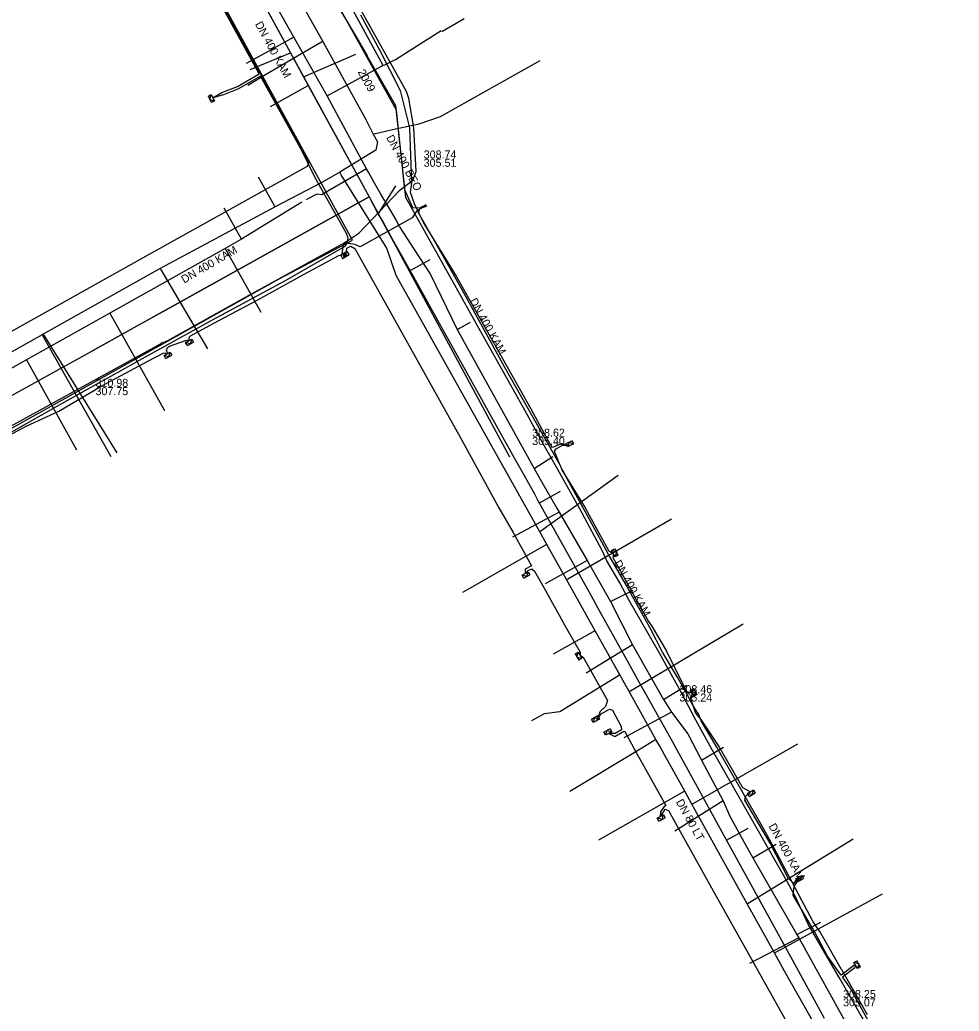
# Model space of a CAD drawing. Extents: x -600391 to -599491, y -1160176 to -1159402.
# Drawn here: x -600248.7 to -600154.7, y -1160007 to -1159907.9 of the extents above; entities that cross this region are included whole.
import ezdxf

# ---------------------------------------------------------------- set-up
doc = ezdxf.new("R2010")
doc.units = 0
for name, color, linetype in [('28', 7, 'Continuous'), ('31', 7, 'Continuous'), ('CETIN_linie', 7, 'Continuous'), ('Vrstva 1', 7, 'Continuous'), ('Vrstva 12', 7, 'Continuous'), ('Vrstva 13', 7, 'Continuous'), ('Vrstva 15', 7, 'Continuous'), ('Vrstva 16', 7, 'Continuous'), ('Vrstva 19', 7, 'Continuous'), ('Vrstva 42', 7, 'Continuous'), ('Vrstva 43', 7, 'Continuous'), ('Vrstva 44', 7, 'Continuous'), ('Vrstva 55', 7, 'Continuous'), ('Vrstva 58', 7, 'Continuous'), ('Vrstva 9', 7, 'Continuous')]:
    doc.layers.add(name, color=color, linetype=linetype)

# ---------------------------------------------------------------- blocks, each defined once
blk = doc.blocks.new('NN630')
at = {"layer": '31'}
for points in [[(0, -0.7), (-0.7, 0)], [(-0.7, -0.7), (-0.7, 0), (0.7, 0), (0.7, -0.7)], [(-0.7, -0.7), (0.7, -0.7)], [(0, -0.7), (0.7, 0)]]:
    blk.add_lwpolyline(points, dxfattribs=at)
blk = doc.blocks.new('NN620')
at = {"layer": '28'}
for points in [[(0.75, 0), (-0.75, 0)], [(-0.75, 0), (-0.75, -0.75)], [(0.75, -0.75), (0.75, 0)], [(-0.75, -0.75), (0.75, -0.75)], [(0.37, -0.18), (-0.38, -0.18)], [(-0.38, -0.18), (-0.38, -0.56)], [(-0.38, -0.56), (0.37, -0.56)], [(0.32, -0.23), (-0.33, -0.23)], [(-0.33, -0.23), (-0.33, -0.51)], [(-0.33, -0.51), (0.32, -0.51)], [(0.27, -0.27), (-0.28, -0.27)], [(-0.28, -0.27), (-0.28, -0.46)], [(-0.28, -0.46), (0.27, -0.46)], [(0.23, -0.32), (-0.23, -0.32)], [(-0.23, -0.32), (-0.23, -0.42)], [(-0.23, -0.42), (0.23, -0.42)], [(-0.19, -0.37), (0.19, -0.37)], [(0.23, -0.42), (0.23, -0.32)], [(0.27, -0.46), (0.27, -0.27)], [(0.32, -0.51), (0.32, -0.23)], [(0.37, -0.56), (0.37, -0.18)]]:
    blk.add_lwpolyline(points, dxfattribs=at)

msp = doc.modelspace()

# ---------------------------------------------------------------- linework, layer by layer
at = {"layer": 'CETIN_linie'}
for p, q in [((-600181.06, -1159977.93), (-600182.53, -1159975.15)), ((-600171.88, -1159994.13), (-600176.71, -1159985.63)), ((-600156.94, -1160020.68), (-600166.6, -1160003.83))]:
    msp.add_line(p, q, dxfattribs=at)
for points in [[(-600229.22, -1159878.49), (-600229.51, -1159878.56), (-600231.76, -1159879.81), (-600225.26, -1159891.62), (-600224.22, -1159891.95), (-600223.98, -1159892.52), (-600224.15, -1159893.48), (-600217.61, -1159905.3), (-600215.04, -1159909.61), (-600213.93, -1159911.53)], [(-600195.003, -1159952.628), (-600196.31, -1159950.3), (-600198.14, -1159947.01), (-600203.06, -1159938.22), (-600203.1, -1159938.16), (-600210.05, -1159925.68), (-600211.06, -1159916.52), (-600213.93, -1159911.53)], [(-600190.41, -1159960.98), (-600192.65, -1159956.82), (-600195.003, -1159952.628)], [(-600182.53, -1159975.15), (-600184.7, -1159971.24), (-600187.71, -1159965.99), (-600188.67, -1159964.22), (-600189.97, -1159962.01), (-600190.41, -1159960.98)], [(-600176.71, -1159985.63), (-600179.43, -1159980.91), (-600181.06, -1159977.93)], [(-600166.6, -1160003.83), (-600169.8, -1159998.34), (-600171.08, -1159995.6), (-600171.88, -1159994.13)]]:
    msp.add_lwpolyline(points, dxfattribs=at)
at = {"layer": 'Vrstva 1'}
for points in [[(-600227.38, -1159900.62), (-600213.74, -1159925.63)], [(-600225.623, -1159912.896), (-600221.592, -1159911.232)], [(-600220.3, -1159913.602), (-600215.079, -1159911.361)], [(-600223.592, -1159916.572), (-600219.821, -1159914.48)], [(-600212.817, -1159927.336), (-600211.075, -1159924.52)], [(-600213.74, -1159925.63), (-600241.48, -1159941.06)], [(-600213.74, -1159925.63), (-600199.68, -1159951.62)], [(-600207.656, -1159931.9), (-600209.718, -1159933.049)], [(-600194.628, -1159955.067), (-600196.741, -1159956.233)], [(-600175.847, -1159988.76), (-600178.01, -1159989.96)]]:
    msp.add_lwpolyline(points, dxfattribs=at)
at = {"layer": 'Vrstva 13'}
for p, q in [((-600216.681, -1159923.158), (-600218.452, -1159924.183)), ((-600216.52, -1159923.42), (-600216.681, -1159923.158)), ((-600211.95, -1159930.74), (-600216.52, -1159923.42)), ((-600234.63, -1159932.796), (-600229.9, -1159940.808)), ((-600246.455, -1159939.412), (-600239.571, -1159951.564)), ((-600246.329, -1159939.337), (-600238.986, -1159951.215))]:
    msp.add_line(p, q, dxfattribs=at)
for points in [[(-600235.77, -1159878.73), (-600234.17, -1159881.51), (-600232.367, -1159884.809), (-600230.48, -1159888.26), (-600223.703, -1159900.561), (-600223.01, -1159901.82), (-600218.371, -1159910.085), (-600214.068, -1159917.894), (-600213.34, -1159919.34), (-600212.9, -1159920.13), (-600213.06, -1159920.96), (-600216.681, -1159923.158)], [(-600218.371, -1159910.085), (-600218.497, -1159910.161), (-600223.929, -1159913.33), (-600225.883, -1159914.469)], [(-600213.34, -1159919.34), (-600213.108, -1159919.284), (-600211.41, -1159918.88), (-600208.74, -1159918.3), (-600206.59, -1159917.58), (-600196.63, -1159911.975)], [(-600218.452, -1159924.183), (-600223.136, -1159926.626), (-600234.63, -1159932.796), (-600246.329, -1159939.337), (-600246.455, -1159939.412), (-600258.475, -1159946.157), (-600268.657, -1159951.909), (-600271.06, -1159953.3), (-600271.84, -1159953.73)], [(-600223.136, -1159926.626), (-600223.211, -1159926.502), (-600224.793, -1159923.665)], [(-600154.709, -1160034.079), (-600157.474, -1160029.081), (-600161.178, -1160022.525), (-600161.396, -1160022.14), (-600162.074, -1160020.939), (-600165.91, -1160014.151), (-600169.665, -1160007.505), (-600172.186, -1160003.043), (-600173.2, -1160001.214), (-600175.931, -1159996.29), (-600181.445, -1159986.347), (-600182.167, -1159985.045), (-600184.183, -1159981.41), (-600184.671, -1159980.537), (-600185.044, -1159979.869), (-600187.721, -1159975.079), (-600188.649, -1159973.419), (-600191.123, -1159968.992), (-600193.986, -1159963.868), (-600195.946, -1159960.361), (-600196.653, -1159959.101), (-600211.015, -1159933.486), (-600211.95, -1159930.74)], [(-600196.653, -1159959.101), (-600196.546, -1159959.024), (-600188.833, -1159953.438)], [(-600193.986, -1159963.868), (-600193.852, -1159963.796), (-600183.488, -1159957.804)], [(-600195.946, -1159960.361), (-600196.15, -1159960.479), (-600204.408, -1159965.177)], [(-600191.123, -1159968.992), (-600191.316, -1159969.1), (-600195.34, -1159971.346)], [(-600187.721, -1159975.079), (-600187.596, -1159975.004), (-600176.334, -1159968.316)], [(-600188.649, -1159973.419), (-600188.774, -1159973.497), (-600194.665, -1159977.106), (-600196.225, -1159977.317), (-600197.506, -1159978.016)], [(-600185.044, -1159979.869), (-600185.27, -1159980.006), (-600187.221, -1159981.188), (-600193.65, -1159985.062)], [(-600181.445, -1159986.347), (-600181.312, -1159986.273), (-600170.837, -1159980.292)], [(-600182.167, -1159985.045), (-600182.349, -1159985.149), (-600190.803, -1159989.944)], [(-600175.931, -1159996.29), (-600175.815, -1159996.221), (-600165.309, -1159989.808)], [(-600173.2, -1160001.214), (-600173.066, -1160001.143), (-600162.376, -1159995.313)]]:
    msp.add_lwpolyline(points, dxfattribs=at)
at = {"layer": 'Vrstva 16'}
for points in [[(-600220.454, -1159926.15), (-600226.51, -1159929.85), (-600228.15, -1159930.77), (-600239.67, -1159937.23), (-600248.01, -1159941.9), (-600257.72, -1159947.35), (-600266.63, -1159952.34), (-600269.18, -1159953.76), (-600270.17, -1159954.32), (-600274.87, -1159956.95), (-600277.66, -1159958.52), (-600294.25, -1159967.81), (-600301.53, -1159971.89), (-600306.26, -1159974.55)], [(-600226.51, -1159929.85), (-600228.25, -1159926.76)], [(-600228.15, -1159930.77), (-600224.58, -1159937.13)], [(-600239.67, -1159937.23), (-600234.21, -1159946.99)], [(-600248.01, -1159941.9), (-600243.02, -1159950.92)]]:
    msp.add_lwpolyline(points, dxfattribs=at)
at = {"layer": 'Vrstva 19'}
msp.add_line((-600206.46, -1159909.08), (-600204.238, -1159907.796), dxfattribs=at)
for points in [[(-600210.69, -1159928.6), (-600211.071, -1159927.848), (-600212.567, -1159925.332), (-600213.206, -1159924.258), (-600213.809, -1159923.163), (-600213.997, -1159922.82), (-600217.918, -1159915.528), (-600221.258, -1159909.637), (-600225.65, -1159901.89), (-600226.441, -1159900.495), (-600227.057, -1159899.408), (-600227.668, -1159898.317), (-600233.004, -1159888.777), (-600237.397, -1159880.924), (-600237.874, -1159880.113), (-600243.124, -1159871.345), (-600260.994, -1159839.129), (-600261.405, -1159838.349)], [(-600225.044, -1159891.003), (-600224.158, -1159891.278), (-600216.76, -1159904.352), (-600212.351, -1159912.452)], [(-600212.174, -1159912.407), (-600211.104, -1159911.881), (-600206.514, -1159908.994)], [(-600221.258, -1159909.637), (-600224.126, -1159911.251), (-600226.038, -1159912.297)], [(-600217.918, -1159915.528), (-600212.505, -1159912.541)], [(-600212.505, -1159912.541), (-600212.351, -1159912.452), (-600212.174, -1159912.407)], [(-600213.997, -1159922.82), (-600217.852, -1159925.042), (-600218.194, -1159925.244), (-600218.464, -1159925.405), (-600218.959, -1159925.354), (-600219.301, -1159925.523), (-600220.025, -1159925.909)], [(-600210.69, -1159928.6), (-600209.233, -1159930.867), (-600207.61, -1159933.39), (-600204.93, -1159938.88), (-600197.21, -1159952.77), (-600196.46, -1159954.15), (-600194.958, -1159956.747), (-600194.73, -1159957.14), (-600191.92, -1159961.97), (-600189.6, -1159966.08), (-600187.38, -1159970.41), (-600184.29, -1159975.86), (-600183.48, -1159977.13), (-600181.841, -1159979.296), (-600180.487, -1159981.944), (-600178.32, -1159986.01), (-600177.686, -1159987.46), (-600176.241, -1159990.089), (-600175.357, -1159991.697), (-600170.951, -1159999.359), (-600170.74, -1159999.709), (-600162.476, -1160014.618)], [(-600204.93, -1159938.88), (-600203.587, -1159938.131)], [(-600197.21, -1159952.77), (-600195.349, -1159951.573)], [(-600194.73, -1159957.14), (-600199.39, -1159959.65)], [(-600191.92, -1159961.97), (-600196.119, -1159964.292)], [(-600189.6, -1159966.08), (-600187.31, -1159964.93)], [(-600187.38, -1159970.41), (-600190.12, -1159972.08), (-600192.037, -1159973.248)], [(-600184.29, -1159975.86), (-600181.95, -1159974.43)], [(-600183.48, -1159977.13), (-600188.27, -1159979.72)], [(-600180.487, -1159981.944), (-600178.3, -1159980.626)], [(-600178.32, -1159986.01), (-600183.14, -1159989.03)], [(-600175.357, -1159991.697), (-600173.018, -1159990.336)], [(-600170.951, -1159999.359), (-600168.554, -1159998.124)], [(-600170.74, -1159999.709), (-600175.683, -1160002.273)]]:
    msp.add_lwpolyline(points, dxfattribs=at)
at = {"layer": 'Vrstva 42'}
for points in [[(-600216.424, -1159931.321), (-600216.308, -1159930.424), (-600216.054, -1159930.101), (-600214.752, -1159929.245), (-600210.643, -1159924.902), (-600209.361, -1159923.955), (-600209.02, -1159923.095), (-600209.257, -1159918.717), (-600209.765, -1159915.778), (-600209.981, -1159915.075), (-600215.817, -1159904.626), (-600215.065, -1159904.156), (-600205.156, -1159899.006)], [(-600256.845, -1159943.134), (-600235.524, -1159931.234), (-600219.963, -1159922.58), (-600219.91, -1159922.553), (-600219.771, -1159922.24), (-600224.613, -1159913.543), (-600226.808, -1159914.81), (-600228.308, -1159915.429), (-600229.372, -1159915.703), (-600228.462, -1159915.188), (-600226.917, -1159914.584), (-600224.741, -1159913.329), (-600228.715, -1159906.103)], [(-600214.611, -1159907.432), (-600212.658, -1159910.968), (-600210.639, -1159914.994), (-600209.7, -1159918.72), (-600209.481, -1159924.256), (-600209.628, -1159925.165), (-600209.24, -1159926.276), (-600208.255, -1159928.294), (-600205.022, -1159933.559), (-600197.574, -1159946.812), (-600196.021, -1159949.656), (-600195.475, -1159950.635), (-600195.261, -1159950.597), (-600194.503, -1159950.275), (-600193.588, -1159950.465), (-600194.393, -1159950.489), (-600195.091, -1159950.838), (-600195.229, -1159951.047), (-600194.44, -1159952.987), (-600192.123, -1159956.71), (-600189.779, -1159960.962), (-600189.305, -1159961.292), (-600189.355, -1159961.687), (-600188.121, -1159963.89), (-600187.171, -1159965.647), (-600185.773, -1159968.09), (-600185.41, -1159968.597), (-600184.014, -1159970.96), (-600181.976, -1159975.067), (-600181.409, -1159975.25), (-600181.558, -1159975.859), (-600181.094, -1159977.232), (-600180.566, -1159977.871), (-600178.742, -1159980.579), (-600176.396, -1159984.672), (-600175.6, -1159985.09)], [(-600216.006, -1159931.083), (-600215.981, -1159930.743), (-600215.564, -1159930.533), (-600215.159, -1159930.786), (-600204.469, -1159949.943), (-600200.752, -1159956.715), (-600199.318, -1159959.185), (-600197.485, -1159962.501), (-600198.14, -1159962.834), (-600198.124, -1159963.263), (-600197.823, -1159962.959), (-600197.464, -1159962.799), (-600197.184, -1159963.035), (-600196.266, -1159964.671), (-600194.03, -1159968.702), (-600192.64, -1159971.139), (-600192.641, -1159971.45), (-600192.34, -1159971.64), (-600189.89, -1159975.978), (-600190.086, -1159976.581), (-600190.636, -1159977.087), (-600191.005, -1159977.992), (-600190.512, -1159977.304), (-600189.694, -1159976.835), (-600189.392, -1159976.927), (-600188.514, -1159978.587), (-600188.503, -1159978.901), (-600189.129, -1159979.277), (-600189.771, -1159979.278), (-600189.14, -1159979.575), (-600188.248, -1159979.039), (-600188.16, -1159979.069), (-600187.036, -1159981.184), (-600185.03, -1159984.738), (-600184.067, -1159986.458), (-600184.208, -1159986.556), (-600184.594, -1159987.102), (-600184.607, -1159987.552), (-600184.331, -1159987.163), (-600184.11, -1159986.851), (-600183.788, -1159986.956), (-600179.488, -1159994.714), (-600175.799, -1160001.305), (-600173.918, -1160004.64), (-600170.775, -1160010.216)], [(-600252.06, -1159950.67), (-600248.06, -1159948.56), (-600244.79, -1159947.06), (-600240.47, -1159944.5), (-600235.82, -1159942.02), (-600234.35, -1159941.25), (-600234.16, -1159941.21), (-600234.065, -1159941.307), (-600233.95, -1159941.315), (-600233.894, -1159941.229), (-600233.99, -1159940.93), (-600233.89, -1159940.68), (-600233.69, -1159940.53), (-600232.12, -1159939.98), (-600231.96, -1159939.96), (-600231.789, -1159940.01), (-600231.724, -1159939.913), (-600231.74, -1159939.78), (-600231.713, -1159939.612), (-600231.61, -1159939.51), (-600229.2, -1159938.22), (-600224.86, -1159935.91), (-600220.25, -1159933.35), (-600216.75, -1159931.469), (-600216.607, -1159931.445)], [(-600163.74, -1160008.1), (-600165.61, -1160004.7), (-600166.392, -1160003.602), (-600165.159, -1160002.67), (-600165.06, -1160002.47), (-600165.28, -1160002.511), (-600166.508, -1160003.439), (-600167.87, -1160001.53), (-600169.16, -1159999.12), (-600171.31, -1159995.43), (-600171.215, -1159994.554), (-600170.773, -1159993.862), (-600170.75, -1159993.64), (-600170.942, -1159993.755), (-600171.265, -1159994.262), (-600171.83, -1159993.75), (-600173.63, -1159990.22), (-600176.14, -1159985.94), (-600176.09, -1159985.56), (-600175.6, -1159985.09)]]:
    msp.add_lwpolyline(points, dxfattribs=at)
at = {"layer": 'Vrstva 44'}
msp.add_lwpolyline([(-600252.21, -1159950.64), (-600245.09, -1159946.6), (-600236.11, -1159941.6), (-600229.4, -1159937.92), (-600222.09, -1159933.97), (-600216.12, -1159930.56), (-600215.94, -1159930.27), (-600215.83, -1159929.73), (-600216.04, -1159929.23), (-600219.16, -1159923.66), (-600221.38, -1159919.15), (-600224.31, -1159913.83), (-600229.51, -1159904.42)], dxfattribs=at)
at = {"layer": 'Vrstva 55'}
for points in [[(-600208.068, -1159926.408), (-600208.44, -1159926.61), (-600208.644, -1159926.75), (-600209.38, -1159926.73), (-600210.16, -1159924.93), (-600211, -1159916.94), (-600218.58, -1159903.31), (-600223.67, -1159893.79), (-600223.81, -1159893.86), (-600223.699, -1159893.694), (-600224.26, -1159892.22), (-600229.65, -1159881.81), (-600230.02, -1159880.76), (-600230.26, -1159878.76), (-600229.908, -1159877.587), (-600229.5, -1159877.369), (-600229.69, -1159876.616), (-600229.659, -1159876.093), (-600229.51, -1159875.95)], [(-600207.976, -1159926.533), (-600208.5, -1159926.76), (-600208.95, -1159927), (-600209.42, -1159927.7), (-600212.006, -1159929.154), (-600214.63, -1159930.63), (-600215.17, -1159930.37), (-600216.2, -1159930.22), (-600225.82, -1159935.52), (-600233.89, -1159940.02), (-600234.43, -1159940.24), (-600234.54, -1159940.2)], [(-600163.88, -1160007.39), (-600166.44, -1160002.91), (-600166.469, -1160002.868), (-600168.65, -1159999.07), (-600169.31, -1159998.1), (-600170.75, -1159995.41), (-600172.94, -1159991.22), (-600173.92, -1159989.43), (-600174.697, -1159988.076), (-600178.44, -1159981.55), (-600178.94, -1159980.65), (-600180.51, -1159977.99), (-600180.8, -1159977.32), (-600180.863, -1159977.221), (-600180.9, -1159977.21), (-600180.908, -1159977.15), (-600181.35, -1159976.45), (-600182.13, -1159975), (-600182.86, -1159973.7), (-600184.4, -1159971.13), (-600185.62, -1159968.74), (-600185.98, -1159968.07), (-600187.86, -1159964.75), (-600187.98, -1159964.48), (-600189.81, -1159961.31), (-600191.521, -1159958.181), (-600193.95, -1159953.74), (-600194.328, -1159953.04), (-600194.37, -1159952.99), (-600194.42, -1159952.87), (-600194.72, -1159952.28), (-600195.33, -1159951.2), (-600200.17, -1159942.69), (-600204.43, -1159934.9), (-600206.076, -1159932.004), (-600208.79, -1159927.23), (-600208.66, -1159926.77), (-600208.56, -1159926.73)], [(-600208.56, -1159926.73), (-600208.005, -1159926.473)], [(-600234.495, -1159940.287), (-600234.63, -1159940.36), (-600256.76, -1159952.48), (-600267.29, -1159958.55), (-600277.51, -1159963.86), (-600297.75, -1159975.17), (-600300.78, -1159977.22), (-600301.45, -1159978.98), (-600301.64, -1159981.14), (-600301.82, -1159983.47), (-600300.78, -1159985.15), (-600299.508, -1159987.201)]]:
    msp.add_lwpolyline(points, dxfattribs=at)
at = {"layer": 'Vrstva 58'}
msp.add_lwpolyline([(-600256.663, -1160038.315), (-600300.347, -1159981.753), (-600300.188, -1159978.424), (-600298.445, -1159975.809), (-600265.647, -1159957.741), (-600222.742, -1159933.825), (-600215.406, -1159929.961), (-600220.159, -1159921.243), (-600245.973, -1159874.147)], dxfattribs=at)
at = {"layer": 'Vrstva 9'}
for points in [[(-600227.38, -1159900.62), (-600225.878, -1159903.375), (-600225.877, -1159903.377), (-600221.797, -1159910.856), (-600221.592, -1159911.232), (-600220.457, -1159913.315), (-600220.3, -1159913.602), (-600220.054, -1159914.052), (-600219.821, -1159914.48), (-600213.74, -1159925.63)], [(-600241.47, -1159941.03), (-600236.951, -1159938.52), (-600233.756, -1159936.746), (-600213.74, -1159925.63)], [(-600213.74, -1159925.63), (-600212.817, -1159927.336), (-600212.274, -1159928.292)], [(-600212.274, -1159928.292), (-600211.394, -1159929.875), (-600209.671, -1159932.961), (-600206.72, -1159938.254), (-600199.221, -1159951.705)], [(-600264.49, -1159953.81), (-600249.908, -1159945.715), (-600246.233, -1159943.674), (-600241.47, -1159941.03)], [(-600199.221, -1159951.705), (-600198.569, -1159952.873), (-600197.206, -1159955.32), (-600196.846, -1159955.965), (-600191.605, -1159965.363), (-600190.876, -1159966.674), (-600187.982, -1159971.861), (-600186.907, -1159973.792), (-600184.009, -1159978.988), (-600183.425, -1159980.037)], [(-600183.425, -1159980.037), (-600182.944, -1159980.912), (-600180.39, -1159985.557), (-600178.242, -1159989.465), (-600175.214, -1159994.977), (-600171.721, -1160001.331), (-600171.384, -1160001.945), (-600168.205, -1160007.729)]]:
    msp.add_lwpolyline(points, dxfattribs=at)

# ---------------------------------------------------------------- block references
at = {"layer": 'Vrstva 43'}
for name, p, xscale, yscale, rotation in [('NN630', (-600229.372, -1159915.703), 0.5, 0.5, -61.000000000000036), ('NN620', (-600216.258, -1159931.255), 0.5, 0.5, 29.999999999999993), ('NN630', (-600231.789, -1159940.01), 0.5, 0.5, 29.999999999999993), ('NN630', (-600233.95, -1159941.315), 0.5, 0.5, 29.00000000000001), ('NN630', (-600193.589, -1159950.465), 0.5, 0.5, -153), ('NN630', (-600189.305, -1159961.292), 0.5000000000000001, 0.4999999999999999, 119), ('NN630', (-600198.124, -1159963.263), 0.5000000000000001, 0.4999999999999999, 28), ('NN630', (-600192.641, -1159971.45), 0.5, 0.5, -59.99999999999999), ('NN630', (-600181.409, -1159975.25), 0.5, 0.5, 119.99999999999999), ('NN630', (-600191.005, -1159977.992), 0.5000000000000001, 0.4999999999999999, -151), ('NN630', (-600189.771, -1159979.278), 0.5000000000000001, 0.4999999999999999, -151), ('NN630', (-600175.6, -1159985.09), 0.5, 0.5, 31), ('NN630', (-600184.607, -1159987.552), 0.5, 0.5, 29.00000000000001), ('NN630', (-600170.75, -1159993.64), 0.5, 0.5, 29.999999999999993), ('NN630', (-600165.06, -1160002.47), 0.5, 0.5, 119.99999999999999)]:
    msp.add_blockref(name, p, dxfattribs=dict(at, xscale=xscale, yscale=yscale, rotation=rotation))

# ---------------------------------------------------------------- texts
at = {"layer": 'Vrstva 12'}
for s, rotation, p in [('DN 400 KAM', 298.6256, (-600225.178, -1159908.346)), ('DN 400 BEO', 298.39643, (-600212.052, -1159919.683)), ('DN 400 KAM', 30.19488, (-600232.239, -1159934.294)), ('DN 400 KAM', 299.14093, (-600203.71, -1159936.014)), ('DN 400 KAM', 299.14718, (-600189.27, -1159962.21)), ('DN 400 KAM', 298.78206, (-600173.802, -1159988.526))]:
    msp.add_text(s, height=0.8, rotation=rotation, dxfattribs=at).set_placement(p)
for s, p in [('308.74', (-600208.278, -1159921.779)), ('305.51', (-600208.278, -1159922.611)), ('310.98', (-600241.105, -1159944.611)), ('307.75', (-600241.105, -1159945.443)), ('308.62', (-600197.429, -1159949.598)), ('305.40', (-600197.429, -1159950.43)), ('308.46', (-600182.692, -1159975.243)), ('305.24', (-600182.692, -1159976.075)), ('308.25', (-600166.323, -1160005.719)), ('305.07', (-600166.323, -1160006.551))]:
    msp.add_text(s, height=0.8, dxfattribs=at).set_placement(p)
at = {"layer": 'Vrstva 15'}
for s, rotation, p in [('2009', 298.85479, (-600214.903, -1159913.125)), ('DN 80 LT', 299.00975, (-600183.07, -1159986.103))]:
    msp.add_text(s, height=0.8, rotation=rotation, dxfattribs=at).set_placement(p)

doc.saveas('drawing.dxf')
